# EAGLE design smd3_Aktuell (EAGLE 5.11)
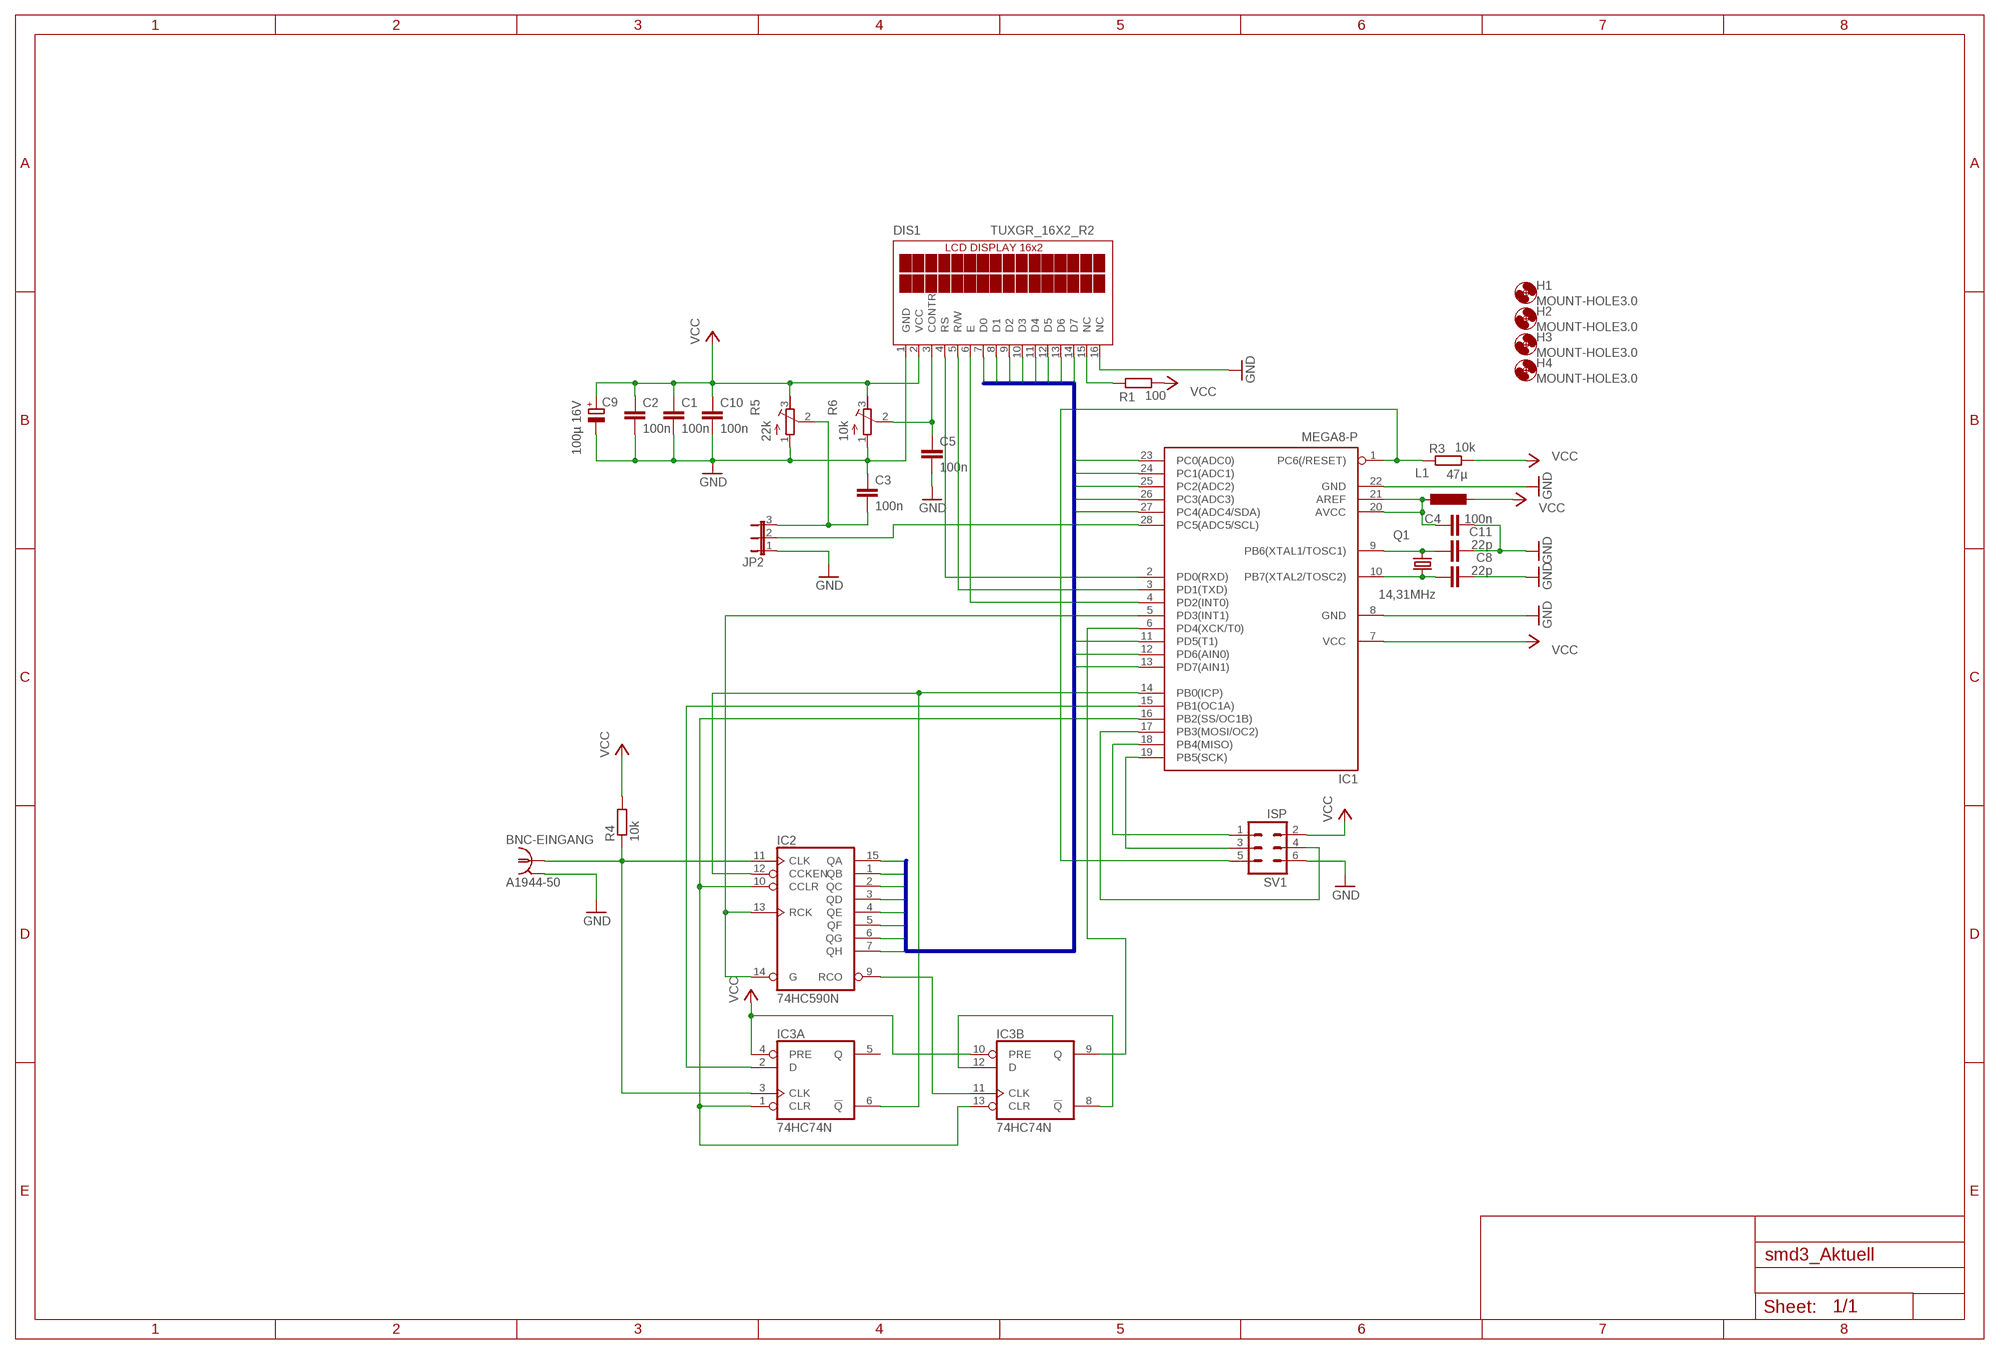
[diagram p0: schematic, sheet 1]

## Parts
BNC-EINGANG  A1944-50  [A1944]
C1  100n  C-EUC1206K  [C1206K]
C2  100n  C-EUC1206K  [C1206K]
C3  100n  C-EUC1206K  [C1206K]
C4  100n  C-EUC1206K  [C1206K]
C5  100n  C-EUC1206K  [C1206K]
C8  22p  C-EUC1206K  [C1206K]
C9  100µ 16V  CPOL-EUE5-8.5  [E5-8,5]
C10  100n  C-EUC1206K  [C1206K]
C11  22p  C-EUC1206K  [C1206K]
DIS1  TUXGR_16X2_R2  [TUXGR_16X2_R2]
H1  MOUNT-HOLE3.0  [3,0]
H2  MOUNT-HOLE3.0  [3,0]
H3  MOUNT-HOLE3.0  [3,0]
H4  MOUNT-HOLE3.0  [3,0]
IC1  MEGA8-P  [DIL28-3]
IC2  74HC590N  [DIL16]
IC3  74HC74N  [DIL14]
JP2  JP2E  [JP2]
L1  47µ  L-EU0204/7  [0204/7]
Q1  14,31MHz  CRYSTALHC49S  [HC49/S]
R1  100  R-EU_0204/7  [0204/7]
R3  10k  R-EU_0204/7  [0204/7]
R4  10k  R-EU_0204/7  [0204/7]
R5  22k  R-TRIMM3296Y  [RTRIM3296Y]
R6  10k  R-TRIMM3296Y  [RTRIM3296Y]
SV1  ISP  ML6  [ML6]

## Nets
0: DIS1.7(D0) IC1.23(PC0(ADC0)) IC2.15(QA)
1: DIS1.8(D1) IC1.24(PC1(ADC1)) IC2.1(QB)
2: DIS1.9(D2) IC1.25(PC2(ADC2)) IC2.2(QC)
3: DIS1.10(D3) IC1.26(PC3(ADC3)) IC2.3(QD)
4: DIS1.11(D4) IC1.27(PC4(ADC4/SDA)) IC2.4(QE)
5: DIS1.12(D5) IC1.11(PD5(T1)) IC2.5(QF)
6: DIS1.13(D6) IC1.12(PD6(AIN0)) IC2.6(QG)
7: DIS1.14(D7) IC1.13(PD7(AIN1)) IC2.7(QH)
GND: BNC-EINGANG.2(GND) C1.2 C2.2 C3.1 C4.2 C5.2 C8.2 C9.- C10.2 C11.2 DIS1.1(GND) DIS1.16(NC) IC1.8(GND) IC1.22(GND) JP2.1 R5.1(E) R6.1(E) SV1.6
N$1: BNC-EINGANG.1 IC2.11(CLK) IC3.3(A:CLK) R4.1
N$2: DIS1.6(E) IC1.4(PD2(INT0))
N$3: DIS1.5(R/W) IC1.3(PD1(TXD))
N$4: DIS1.4(RS) IC1.2(PD0(RXD))
N$5: C5.1 DIS1.3(CONTR) R6.2(S)
N$6: IC1.5(PD3(INT1)) IC2.13(RCK) IC2.14(G)
N$7: IC1.14(PB0(ICP)) IC2.12(CCKEN) IC3.6(A:!Q)
N$8: IC1.16(PB2(SS/OC1B)) IC2.10(CCLR) IC3.1(A:CLR) IC3.13(B:CLR)
N$9: IC2.9(RCO) IC3.11(B:CLK)
N$10: IC1.15(PB1(OC1A)) IC3.2(A:D)
N$11: IC3.8(B:!Q) IC3.12(B:D)
N$12: IC1.6(PD4(XCK/T0)) IC3.9(B:Q)
N$13: IC1.19(PB5(SCK)) SV1.3
N$14: IC1.18(PB4(MISO)) SV1.1
N$15: IC1.17(PB3(MOSI/OC2)) SV1.4
N$16: IC1.1(PC6(/RESET)) R3.1 SV1.5
N$17: C3.2 JP2.3 R5.2(S)
N$18: C4.1 IC1.20(AVCC) IC1.21(AREF) L1.1
N$19: C11.1 IC1.9(PB6(XTAL1/TOSC1)) Q1.2
N$20: C8.1 IC1.10(PB7(XTAL2/TOSC2)) Q1.1
N$21: DIS1.15(NC) R1.1
N$22: IC1.28(PC5(ADC5/SCL)) JP2.2
VCC: C1.1 C2.1 C9.+ C10.1 DIS1.2(VCC) IC1.7(VCC) IC3.4(A:PRE) IC3.10(B:PRE) L1.2 R1.2 R3.2 R4.2 R5.3(A) R6.3(A) SV1.2
Unconnected: IC3.5(A:Q)

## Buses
B$1

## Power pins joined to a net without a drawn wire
GND: BNC-EINGANG.3(GND) BNC-EINGANG.4(GND) BNC-EINGANG.5(GND) IC2.8(GND) IC3.7(P:GND)
VCC: IC2.16(VCC) IC3.14(P:VCC)

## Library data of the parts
BNC-EINGANG = con-coax:A1944-50: BNC CONNECTOR 50 Ohm distributor Buerklin 78F2475
C1-C5 C8 C10 C11 = rcl:C-EU: CAPACITOR, European symbol
C9 = rcl:CPOL-EU: POLARIZED CAPACITOR, European symbol
DIS1 = display-lcd:TUXGR_16X2_R2: Tuxgraphics LCD display 16x2 characters reflective, without background light Source: tuxgr_12x2_r2.pdf
H1-H4 = holes:MOUNT-HOLE: MOUNTING HOLE with drill center marker
IC1 = atmel:MEGA8-P: MICROCONTROLLER 8 Kbytes FLASH, 1 kbytes SRAM, 512 bytes EEPROM, USART, 4-channel 10 bit ADC, 2-channel 8 bit ADC Pin compatible with Atmega48, ATMega88, ATMega168 Source: avr.lbr
IC2 = 74xx-eu:74*590: 8-bit binary COUNTER, output register
IC3 = 74xx-eu:74*74: Dual D type positive edge triggered FLIP FLOP, preset and clear
JP2 = jumper:JP2E: JUMPER
L1 = rcl:L-EU: INDUCTOR, European symbol
Q1 = crystal:CRYSTAL: CRYSTAL
R1 R3 R4 = rcl:R-EU_: RESISTOR, European symbol
R5 R6 = rcl:R-TRIMM: Trimm resistor
SV1 = con-harting-ml:ML6: HARTING

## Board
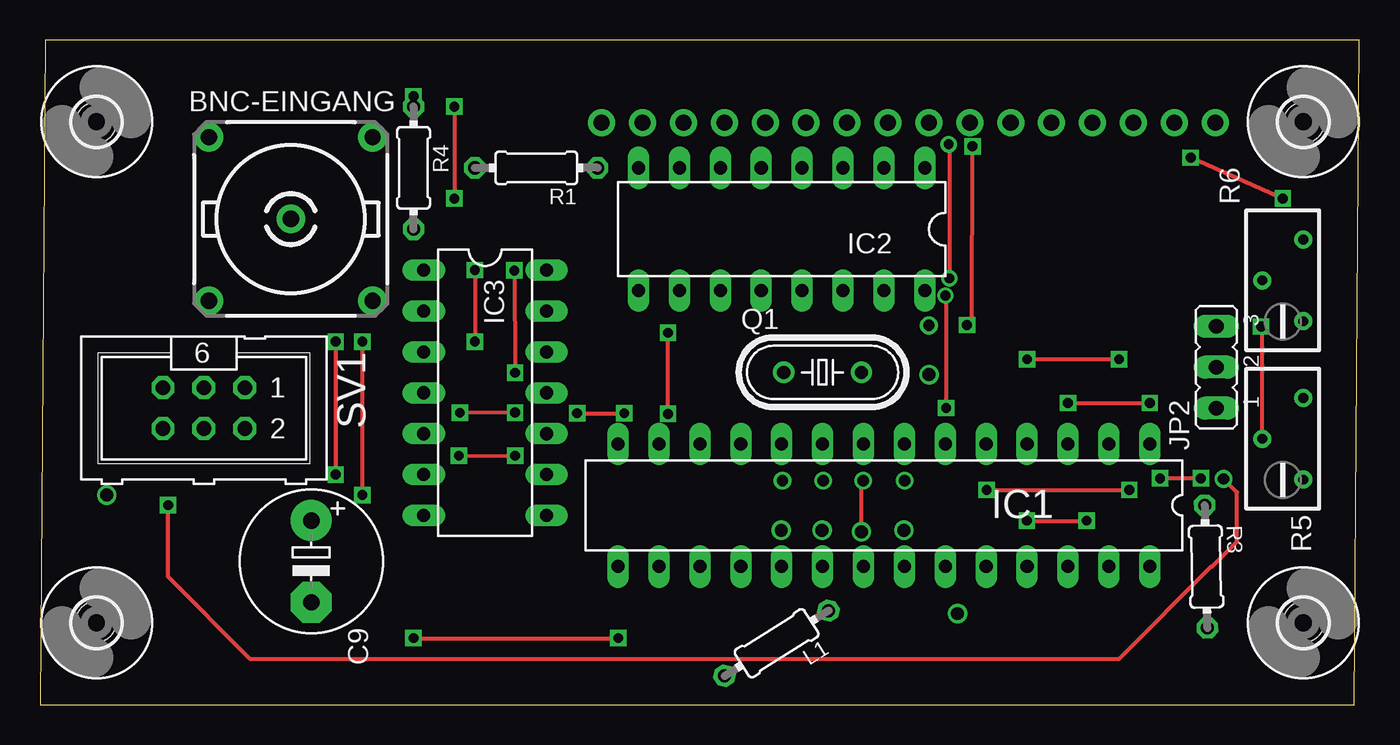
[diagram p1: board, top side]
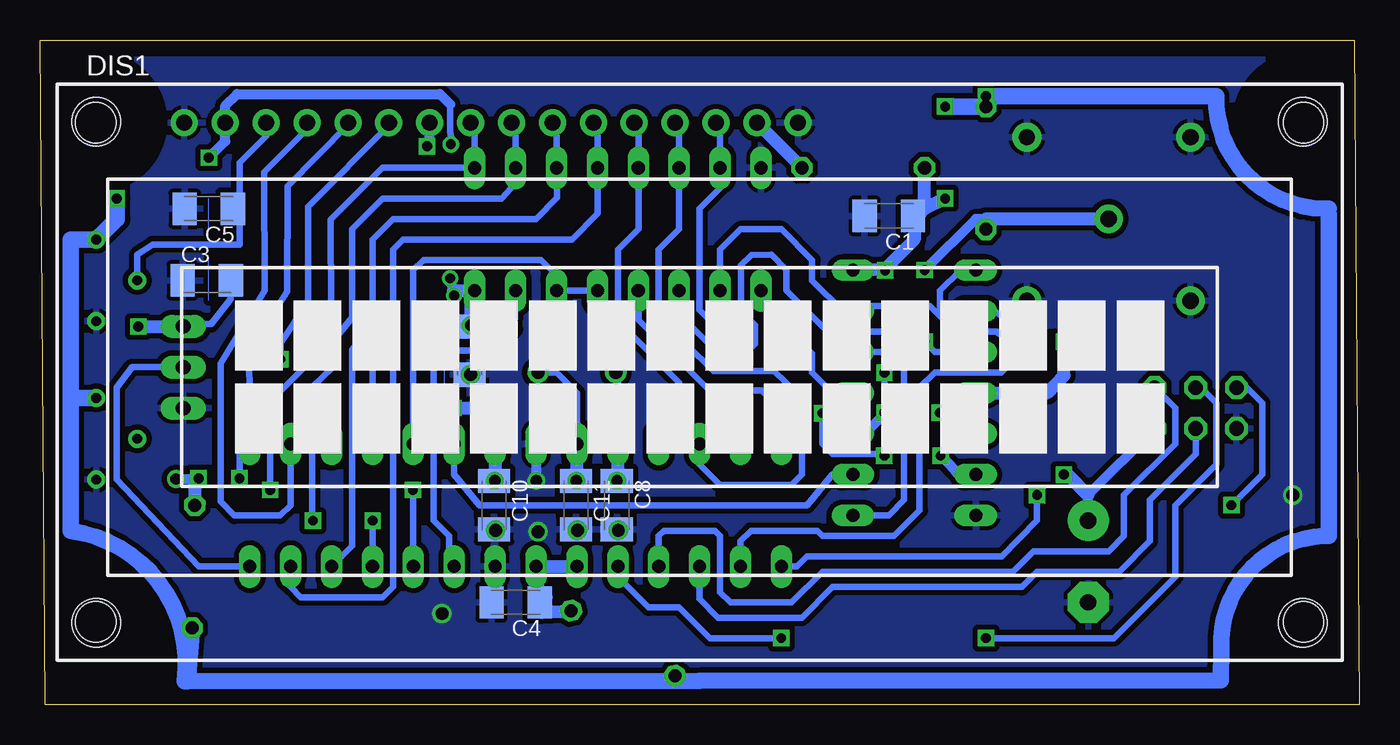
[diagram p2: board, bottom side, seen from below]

Size 81.9 x 41.27 mm. Coordinates in mm from the lower left corner, seen from the top.
Outline: 0,0 81.58,0 81.9,41.27 0.32,41.27 0,0
Copper layers (1*16): Top 0.035mm / dielectric 1.5mm / Bottom 0.035mm
Design rules "Bilex DRU *": minimum track width 10mil, minimum drill 24mil, track to track 10mil, track to pad 10mil, pad to pad 10mil, via to via 10mil, smd to smd 10mil, copper to edge 40mil, drill to drill 8mil, minimum pad ring 10mil, minimum via ring 8mil, stop-mask expansion 4mil, vias tented up to drill 0mil, thermal gap 10mil

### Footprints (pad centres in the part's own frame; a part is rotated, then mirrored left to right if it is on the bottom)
A1944 = drill 1.016 pad 1.778 round: 1 0,0; 2 5.08,5.08; 3 -5.08,5.08; 4 -5.08,-5.08; 5 5.08,-5.08
C1206K = smd 1.5 x 2: 1 -1.5,0; 2 1.5,0
E5-8,5 = drill 1.016 pad 2.54 round: + -2.54,0 | drill 1.016 pad 2.54 octagon: - 2.54,0
TUXGR_16X2_R2 = drill 1 pad 1.676 round: 1 -32,15.5; 2 -29.46,15.5; 3 -26.92,15.5; 4 -24.38,15.5; 5 -21.84,15.5; 6 -19.3,15.5; 7 -16.76,15.5; 8 -14.22,15.5; 9 -11.68,15.5; 10 -9.14,15.5; 11 -6.6,15.5; 12 -4.06,15.5; 13 -1.52,15.5; 14 1.02,15.5; 15 3.56,15.5; 16 6.1,15.5 | hole 2.5: -37.5,-15.5; 37.5,-15.5; -37.5,15.5; 37.5,15.5
3,0 = hole 3: 0,0
DIL28-3 = drill 0.813 long: 1 -16.51,-3.81; 2 -13.97,-3.81; 3 -11.43,-3.81; 4 -8.89,-3.81; 5 -6.35,-3.81; 6 -3.81,-3.81; 7 -1.27,-3.81; 8 1.27,-3.81; 9 3.81,-3.81; 10 6.35,-3.81; 11 8.89,-3.81; 12 11.43,-3.81; 13 13.97,-3.81; 14 16.51,-3.81; 15 16.51,3.81; 16 13.97,3.81; 17 11.43,3.81; 18 8.89,3.81; 19 6.35,3.81; 20 3.81,3.81; 21 1.27,3.81; 22 -1.27,3.81; 23 -3.81,3.81; 24 -6.35,3.81; 25 -8.89,3.81; 26 -11.43,3.81; 27 -13.97,3.81; 28 -16.51,3.81
DIL16 = drill 0.813 long: 1 -8.89,-3.81; 2 -6.35,-3.81; 3 -3.81,-3.81; 4 -1.27,-3.81; 5 1.27,-3.81; 6 3.81,-3.81; 7 6.35,-3.81; 8 8.89,-3.81; 9 8.89,3.81; 10 6.35,3.81; 11 3.81,3.81; 12 1.27,3.81; 13 -1.27,3.81; 14 -3.81,3.81; 15 -6.35,3.81; 16 -8.89,3.81
DIL14 = drill 0.813 long: 1 -7.62,-3.81; 2 -5.08,-3.81; 3 -2.54,-3.81; 4 0,-3.81; 5 2.54,-3.81; 6 5.08,-3.81; 7 7.62,-3.81; 8 7.62,3.81; 9 5.08,3.81; 10 2.54,3.81; 11 0,3.81; 12 -2.54,3.81; 13 -5.08,3.81; 14 -7.62,3.81
JP2 = drill 0.914 long: 1 -2.54,0; 2 0,0; 3 2.54,0
0204/7 = drill 0.813 octagon: 1 -3.81,0; 2 3.81,0
HC49/S = drill 0.813 round: 1 -2.413,0; 2 2.413,0
RTRIM3296Y = drill 0.61 round: 1 1.27,-2.54; 2 -1.27,0; 3 1.27,2.54
ML6 = drill 0.914 octagon: 1 -2.54,-1.27; 2 -2.54,1.27; 3 0,-1.27; 4 0,1.27; 5 2.54,-1.27; 6 2.54,1.27

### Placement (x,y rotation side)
BNC-EINGANG  15.56,30.16 0 top
C1  29.21,30.35 180 bottom
C2  55.24,21.99 270 bottom
C3  71.56,26.35 0 bottom
C4  52.39,6.35 180 bottom
C5  71.44,30.8 180 bottom
C8  46.1,12.38 270 bottom
C9  16.83,8.89 270 top
C10  53.72,12.38 270 bottom
C11  48.64,12.38 270 bottom
DIS1  40.96,20.64 0 bottom
H1  3.49,5.08 0 top
H2  3.49,36.2 0 top
H3  78.42,36.2 0 top
H4  78.42,5.08 0 top
IC1  52.39,12.38 180 top
IC2  46.04,29.53 180 top
IC3  27.62,19.37 270 top
JP2  73.02,20.96 90 top
L1  45.72,3.81 212.1 top
Q1  48.58,20.64 0 top
R1  30.8,33.34 180 top
R3  72.39,8.57 271.3 top
R4  23.18,33.34 90 top
R5  77.15,16.51 0 top
R6  77.15,26.35 0 top
SV1  10.16,18.42 180 top

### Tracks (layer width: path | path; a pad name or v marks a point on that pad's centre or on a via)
0  (via drill 0.61)
  Top 0.254: v57.89,34.68 57.84,23.62 v57.55,23.58
  Bottom 0.406: IC1.23 56.52,8.89 56.52,10.48 57.47,11.43 57.47,22.01 | IC2.15 52.44,23.31 53.66,21.99 56.87,21.99 57.47,22.01 | v57.55,23.58 57.55,21.96 57.47,22.01
  Bottom 0.61: DIS1.7 57.72,34.63 v57.89,34.68
1  (via drill 0.61)
  Top 0.254: v58.77,13.34 v67.63,13.34
  Bottom 0.254: v67.63,13.34 67.58,13.34
  Bottom 0.406: DIS1.8 54.93,35.89 IC2.1 60.64,33.34 63.87,30.11 63.84,24.58 65.09,22.92 65.09,21.36 67.63,18.82 v67.63,13.34 | v58.77,13.34 58.77,8.89 IC1.24
2  (via drill 0.61)
  Top 0.254: v61.26,11.42 v64.97,11.42
  Bottom 0.406: DIS1.9 52.39,35.89 IC2.2 52.39,32.39 53.27,31.43 60.64,31.43 62.55,29.53 62.55,24.05 63.82,22.46 63.79,20.9 65.03,19.72 65.03,11.48 v64.97,11.42 | v61.26,11.42 61.26,8.59 IC1.25
3
  Bottom 0.406: IC1.26 62.55,9.84 62.55,22.03 61.28,23.61 61.28,28.89 60.01,30.16 51.12,30.16 49.8,31.5 IC2.3 49.85,35.89 DIS1.10
4
  Bottom 0.406: IC1.27 66.36,7.3 65.72,6.67 60.64,6.67 60.01,7.3 60.01,28.26 59.37,28.89 48.89,28.89 47.31,30.5 IC2.4 47.31,35.89 DIS1.11
5
  Bottom 0.406: IC1.11 43.5,16.83 42.23,18.1 42.23,20 46.04,23.81 46.04,28.26 44.77,29.53 IC2.5 44.77,35.89 DIS1.12
6
  Bottom 0.406: IC1.12 40.96,14.92 39.69,13.65 35.24,13.65 34.61,14.29 34.61,17.78 34.93,18.73 34.93,19.35 36.33,20.71 40.08,20.71 43.5,24.08 43.5,28.26 42.23,29.53 IC2.6 42.23,35.89 DIS1.13
7  (via drill 0.61)
  Top 0.254: v38.98,18.06 v38.98,23.09
  Bottom 0.406: DIS1.14 39.69,35.89 IC2.7 39.67,33.32 39.67,32.11 40.97,30.81 40.97,24.5 39.68,23.23 39,23.23 39.02,23.21 v38.98,23.09 | IC1.13 38.46,17.37 v38.98,18.06
GND  (via drill 0.7 pad 1.02, 0.8 pad 0.9)
  Top 0.254: v50.99,10.73 50.99,13.8 v51.1,13.91
  Bottom 0.61: v51.1,13.91 51.1,16.15
  other vias: 4.13,13.02 56.96,5.65 46.01,10.83 48.55,10.83 53.63,10.83 55.19,20.5
  pour Bottom (isolate 0.33): -0.95,0.32 82.23,0.32 82.23,41.59 -0.95,41.59
N$1  (via drill 0.61)
  Top 0.254: v26.99,26.99 v26.99,22.54
  Bottom 0.406: IC2.11 42.24,24.27 39.76,21.78 38.13,21.79 37.54,22.39 37.53,23.58 38.39,24.42 38.39,27.3 37.75,27.93 36.51,27.94 35.56,26.99 35.56,25.72 33.03,23.18 28.26,23.18 27.62,22.54 v26.99,22.54 26.35,21.91 IC3.3
  Bottom 0.61: v26.99,26.99 23.81,30.16 23.18,30.16
  Bottom 0.813: R4.1 23.18,30.16 BNC-EINGANG.1
N$2  (via drill 0.61)
  Top 0.254: v61.28,21.45 v66.99,21.45
  Bottom 0.406: DIS1.6 60.26,35.95 65.28,30.92 65.28,25.05 66.98,22.45 v66.99,21.45 | IC1.4 v61.28,21.45
N$3  (via drill 0.61)
  Top 0.254: v63.82,18.73 v68.9,18.73
  Bottom 0.406: DIS1.5 62.8,36.02 66.55,32.21 66.58,25.65 68.93,21.92 v68.9,18.73 | IC1.3 v63.82,18.73
N$4
  Bottom 0.406: 65.34,36.16 DIS1.4 65.38,35.74 65.57,35.49 67.99,33.07 67.97,25.72 70.71,21.2 70.71,12.63 69.85,11.75 67.02,11.75 66.36,12.38 IC1.2
N$5
  Bottom 0.254: C5.1 69.62,30.8 69.53,30.71
  Bottom 0.406: DIS1.3 67.88,35.31 69.53,33.66 69.53,30.71 69.53,30.16 69.53,28.57 74.93,28.57 75.88,27.94 R6.2
N$6
  Bottom 0.406: IC2.13 IC2.14 49.85,26.67 50.8,27.62 58.1,27.62 58.74,26.99 IC1.5
N$7  (via drill 0.61)
  Top 0.254: v25.99,15.46 v29.49,15.46 | v33.34,18.1 v36.27,18.1
  Top 0.406: IC1.14 35.96,16.28
  Bottom 0.406: IC1.14 36.27,16.34 v36.27,18.1 36.27,18.7 37.11,19.5 40.34,19.5 44.77,23.89 IC2.12 | v29.49,15.46 29.45,15.53 29.87,15.56 32.7,15.56 33.34,16.19 v33.34,18.1
  Bottom 0.61: IC3.6 24.88,14.29 25.1,14.55 v25.99,15.46
N$8
  Bottom 0.406: IC1.16 38.42,10.16 37.78,10.79 33.65,10.79 33.34,10.48 28.89,10.48 27.31,12.07 27.31,19.68 26.35,20.64 22.23,20.64 21.59,21.27 21.59,22.49 22.54,23.18 25.08,23.18 26.03,24.13 | 26.03,24.13 26.03,25.72 24.76,26.96 24.13,26.96 IC3.1 | 26.03,24.13 26.67,24.77 31.11,24.77 IC3.13 32.07,24.45 33.97,26.35 33.97,27.62 35.88,29.53 38.42,29.53 39.69,28.26 IC2.10
N$9
  Bottom 0.406: IC3.11 32.7,19.37 33.97,20.64 33.97,21.8 37.14,24.97 IC2.9
N$10  (via drill 0.61)
  Top 0.254: v20,13.02 v20,22.54
  Bottom 0.406: IC1.15 34.93,8.57 34.29,9.21 22.18,9.21 20,11.43 v20,13.02 | IC3.2 22.67,24.45 v20,22.54
N$11
  Bottom 0.406: IC3.12 28.76,21.91 28.26,21.42 28.26,12.7 29.21,11.75 IC3.8
N$12
  Bottom 0.406: IC1.6 56.2,14.29 54.61,12.38 34.29,12.38 32.7,14.29 IC3.9
N$13  (via drill 0.61)
  Top 0.254: v23.18,4.13 v35.89,4.13
  Bottom 0.406: SV1.3 9.84,19.68 8.89,18.73 8.89,14.92 11.43,12.38 11.43,7.94 15.24,4.13 v23.18,4.13 | IC1.19 46.04,7.94 44.13,6.03 42.23,6.03 40.32,4.13 v35.89,4.13
N$14
  Bottom 0.406: IC1.18 43.5,10.48 43.18,10.79 40,10.79 39.69,10.48 39.69,6.99 39.05,6.35 35.24,6.35 33.34,8.25 21.52,8.25 20.25,9.53 15.53,9.53 14.6,10.48 14.6,13.02 11.43,16.19 11.43,18.42 SV1.1
N$15
  Bottom 0.406: IC1.17 40.96,6.57 39.83,5.4 34.61,5.4 32.7,7.3 20.96,7.3 20,8.25 14.9,8.25 13.02,10.16 13.02,12.7 10.16,15.56 SV1.4
N$16  (via drill 0.61, 0.7 pad 1.02)
  Top 0.254: v72.07,14.06 v69.53,14.06 | v7.94,12.38 7.94,7.94 13.02,2.86 66.99,2.86 72.71,8.57 72.77,8.57 74.31,10.11 74.31,13.18 v73.48,14.01
  Bottom 0.406: SV1.5 6.99,19.68 6.03,18.73 6.03,14.29 v7.94,12.38 | v72.07,14.06 72.3,13.88 | v69.53,14.06 69.53,15.56 IC1.1
  Bottom 0.61: v73.48,14.01 72.12,14.01 v72.07,14.06
  Bottom 0.813: R3.1 72.3,14.06 v72.07,14.06
N$17  (via drill 0.61)
  Top 0.254: R5.2 75.88,23.41 v75.81,23.48
  Bottom 0.254: 73.04,23.48 JP2.3
  Bottom 0.406: C3.2 70.06,25.19 71.3,23.62 72.91,23.62 JP2.3
  Bottom 0.813: v75.81,23.48 73.04,23.48
N$18
  Bottom 0.813: 50.48,6.67 50.8,5.71 | 50.48,6.67 51.12,6.03 | 50.48,6.67 50.57,6.67 C4.1 | 50.8,5.71 L1.1 | 50.8,5.71 IC1.21 IC1.20
N$19
  Bottom 0.254: C11.1 48.58,14.03
  Bottom 0.406: Q1.2 49.85,20.64 48.58,19.37 IC1.9
  Bottom 0.813: 48.58,14.03 IC1.9
N$20
  Bottom 0.254: C8.1 46.04,14.03
  Bottom 0.406: IC1.10 46.04,20.13 Q1.1
  Bottom 0.813: 46.04,14.03 IC1.10
N$21
  Bottom 0.813: R1.1 DIS1.15
N$22
  Bottom 0.406: JP2.2 76.2,20.96 77.15,19.68 77.15,13.97 72.07,8.57 IC1.28
N$23
  Bottom 0: 71.44,29.53 71.44,31.43
N$24
  Bottom 0: 71.44,25.08 71.44,27.62
N$25  (via drill 0.7 pad 1.02)
  other vias: 53.68,13.91
N$26
  Bottom 0: 56.79,21.17 56.79,19.61 56.74,19.56
N$27  (via drill 0.7 pad 1.02)
  other vias: 48.62,13.91
N$28  (via drill 0.7 pad 1.02)
  other vias: 46.09,13.91
N$29  (via drill 0.7 pad 1.02)
  other vias: 55.19,23.55
VCC  (via drill 0.61, 0.61 pad 1.02)
  Top 0.254: v25.72,37.15 v25.72,31.43 | v29.49,18.14 v26.05,18.13 | v29.44,26.96 v29.49,20.62 | v18.34,22.54 v18.34,14.29 | v77.15,31.43 v71.44,33.97 | v56.25,18.42 56.25,24.68 v56.21,25.4 | v56.45,26.47 56.45,34.7 v56.4,34.8
  Top 1.016: v23.18,37.78 R4.2
  Bottom 0.254: 1.91,30.48 2.1,30.8 | 53.66,14.03 C10.1 | L1.2 41.22,1.73 40.96,1.47 | 55.33,25.4 55.25,25.4 IC2.16 | 29.48,27.04 v29.44,26.96 | DIS1.2 | 56.25,25.69 56.25,26.27 v56.45,26.47
  Bottom 0.406: v29.49,20.62 v29.49,18.14 | v56.4,34.8 56.4,35.24 56.45,35.58 56.45,37.28
  Bottom 0.61: C2.1 55.25,25.31 55.33,25.4 | v29.49,18.14 29.49,18.06 30.7,16.84 30.94,16.84 30.96,16.82 IC3.10 | SV1.2 16.84,13.03 16.88,12.99 C9.+ | DIS1.2 70.42,34.99 v71.44,33.97 | v56.45,26.47 v56.21,25.4 | 56.45,37.28 57.08,37.92 69.69,37.92 70.42,37.19 DIS1.2
  Bottom 0.813: 53.66,14.03 IC1.7 53.66,17.94 54.14,18.42 v56.25,18.42 | IC3.14 29.48,27.04 27.62,28.89 27.62,29.63 C1.1 27.43,30.35 26.99,30.8 | 26.99,30.8 R1.2 | v25.72,31.43 26.99,30.8 | v26.05,18.13 24.81,19.37 IC3.4 19.37,19.37 18.34,20.44 v18.34,22.54 | v18.34,14.29 18.1,14.29 16.84,13.03 | 56.25,25.69 54.96,25.69 IC2.16
  Bottom 1.016: 72.76,1.45 72.93,1.45 arc-90 80.01,10.79 80.01,19.05 | 80.01,19.05 R5.3 | 80.01,19.05 80.01,28.89 R6.3 77.15,30.16 v77.15,31.43 | 72.76,1.45 40.96,1.47 8.6,1.5 8.57,3.49 arc90 2.22,10.48 1.91,10.48 1.91,30.48 | v23.18,37.78 8.89,37.78 arc-90 2.22,30.8 2.1,30.8 1.91,30.8 | 72.76,1.45 R3.2 | R4.2 v25.72,37.15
